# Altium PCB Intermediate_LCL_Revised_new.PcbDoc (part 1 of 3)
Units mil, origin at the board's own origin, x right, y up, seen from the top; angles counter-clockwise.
Board outline 12850 x 6950 mil, 4 copper layers (Top Layer, Lay1, gnd, Bottom Layer), stack 23.756 mil thick; 473 components, 243 nets, 1278 pads, 73 vias.
Unrouted connection lines stored in the file: 289.
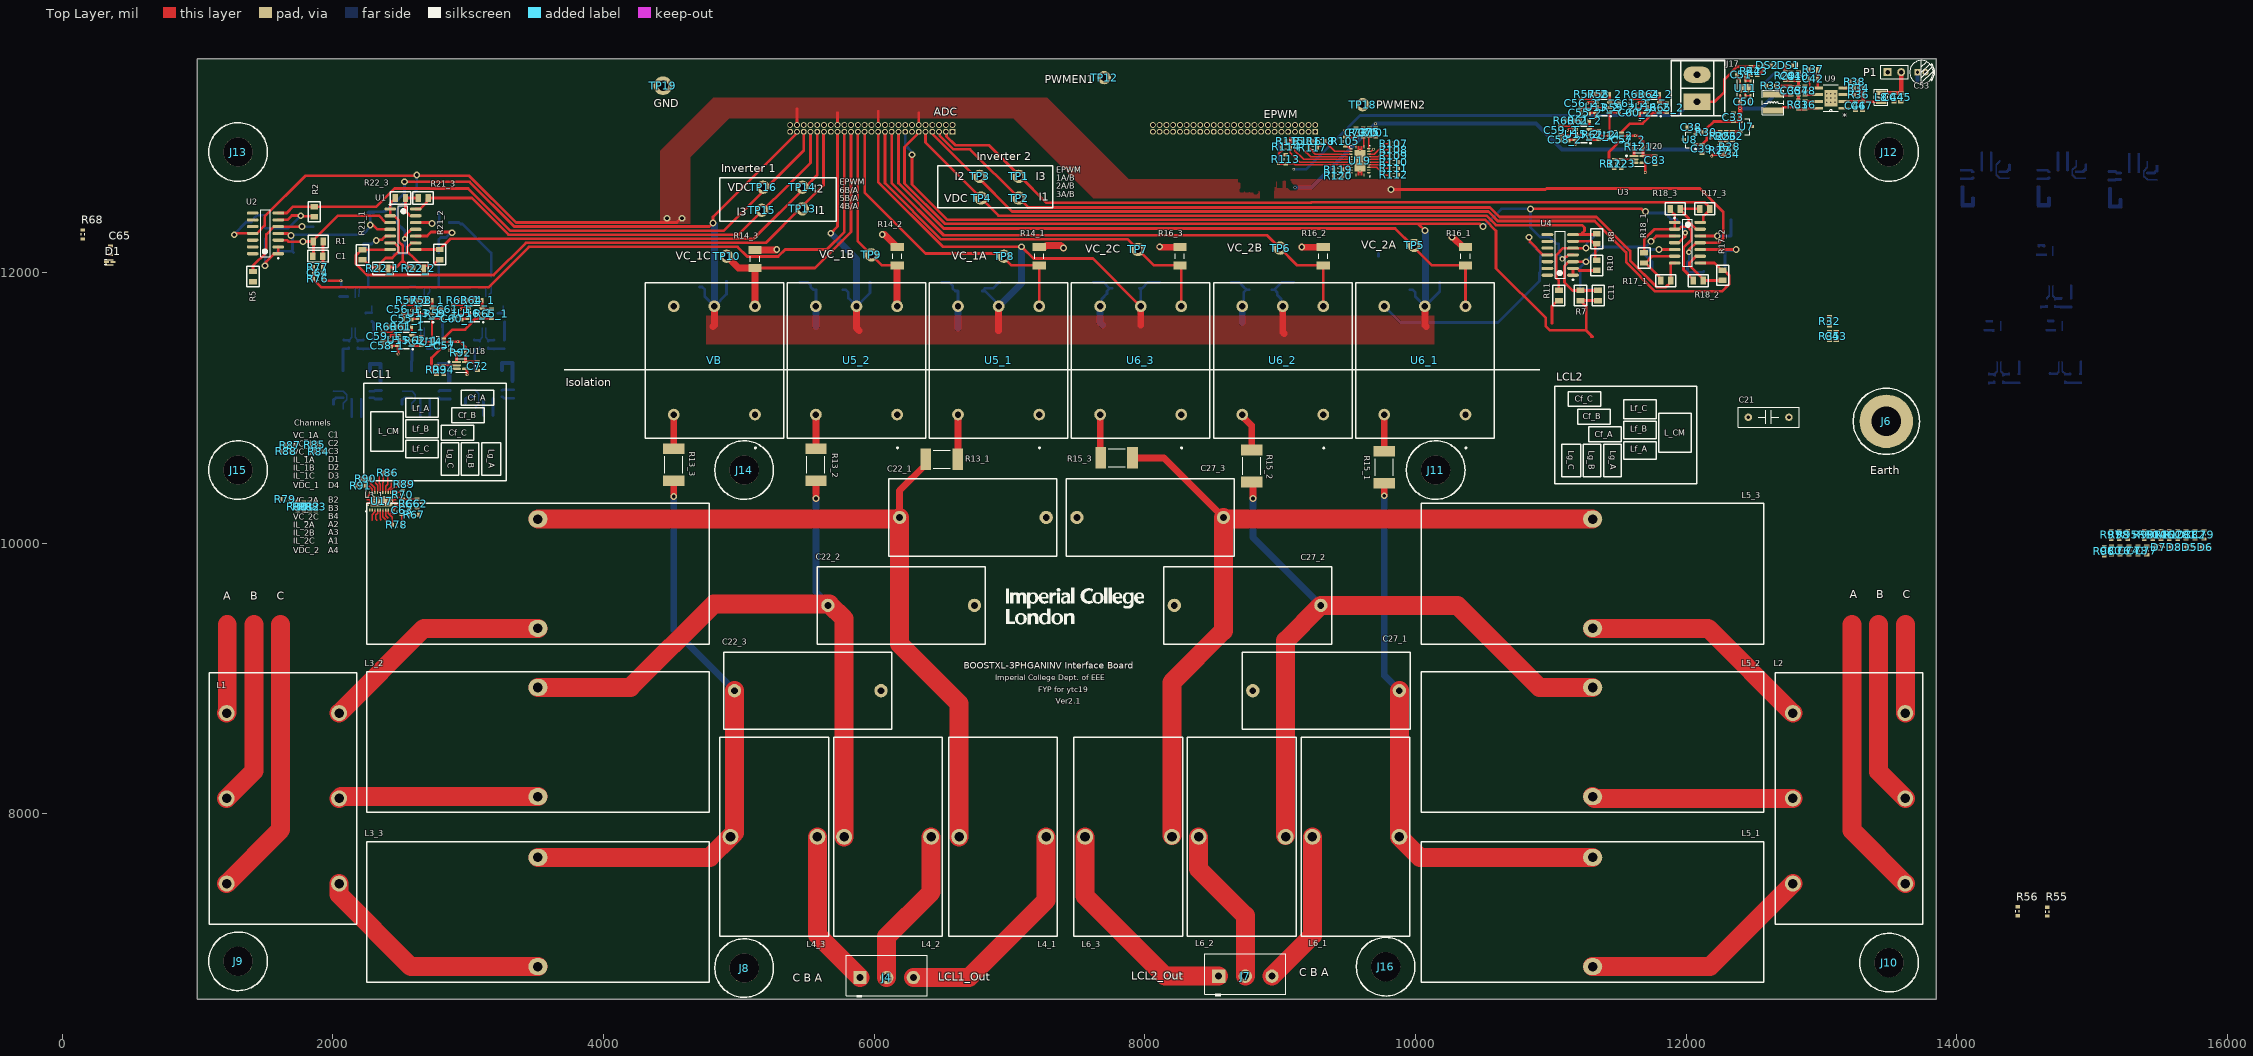
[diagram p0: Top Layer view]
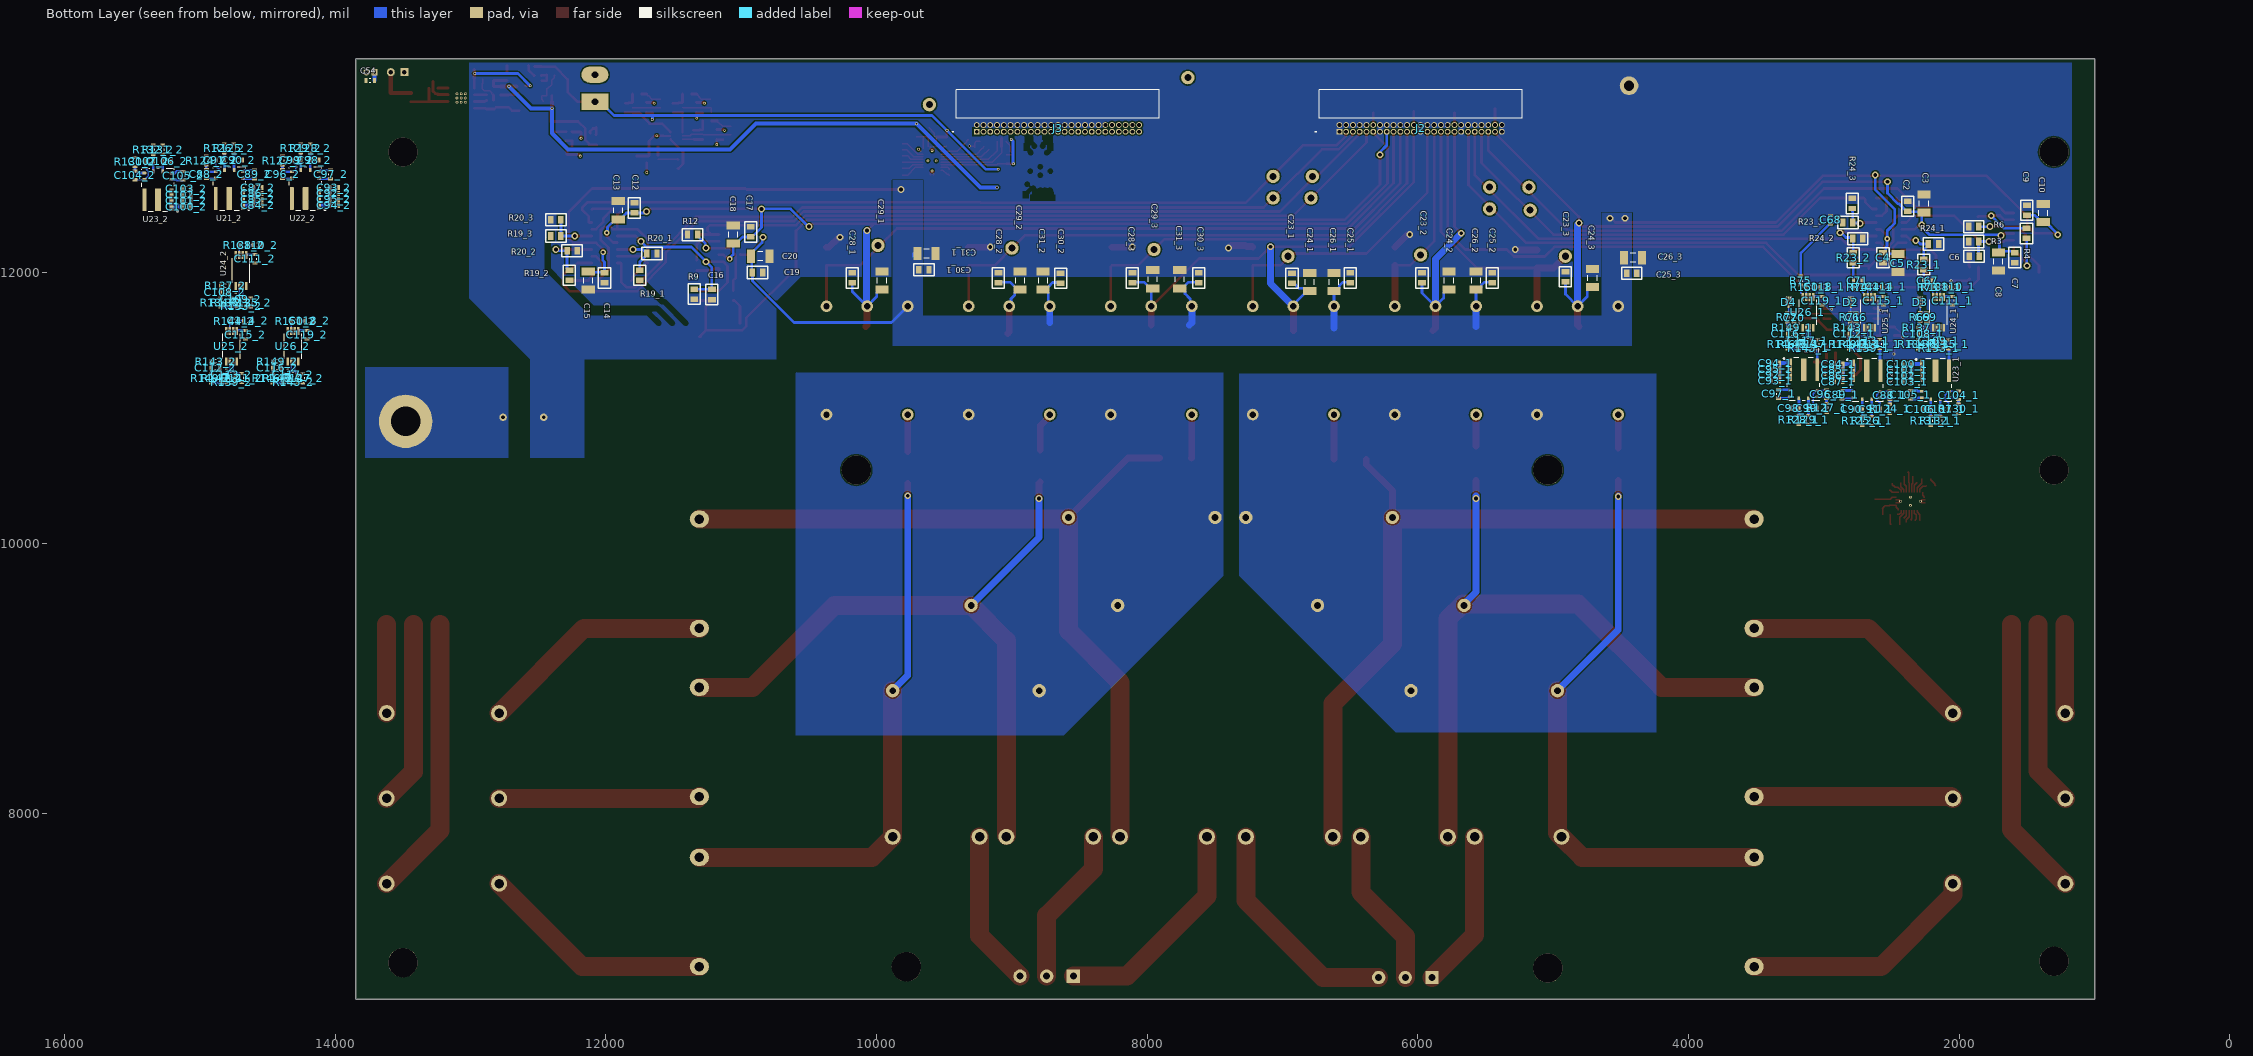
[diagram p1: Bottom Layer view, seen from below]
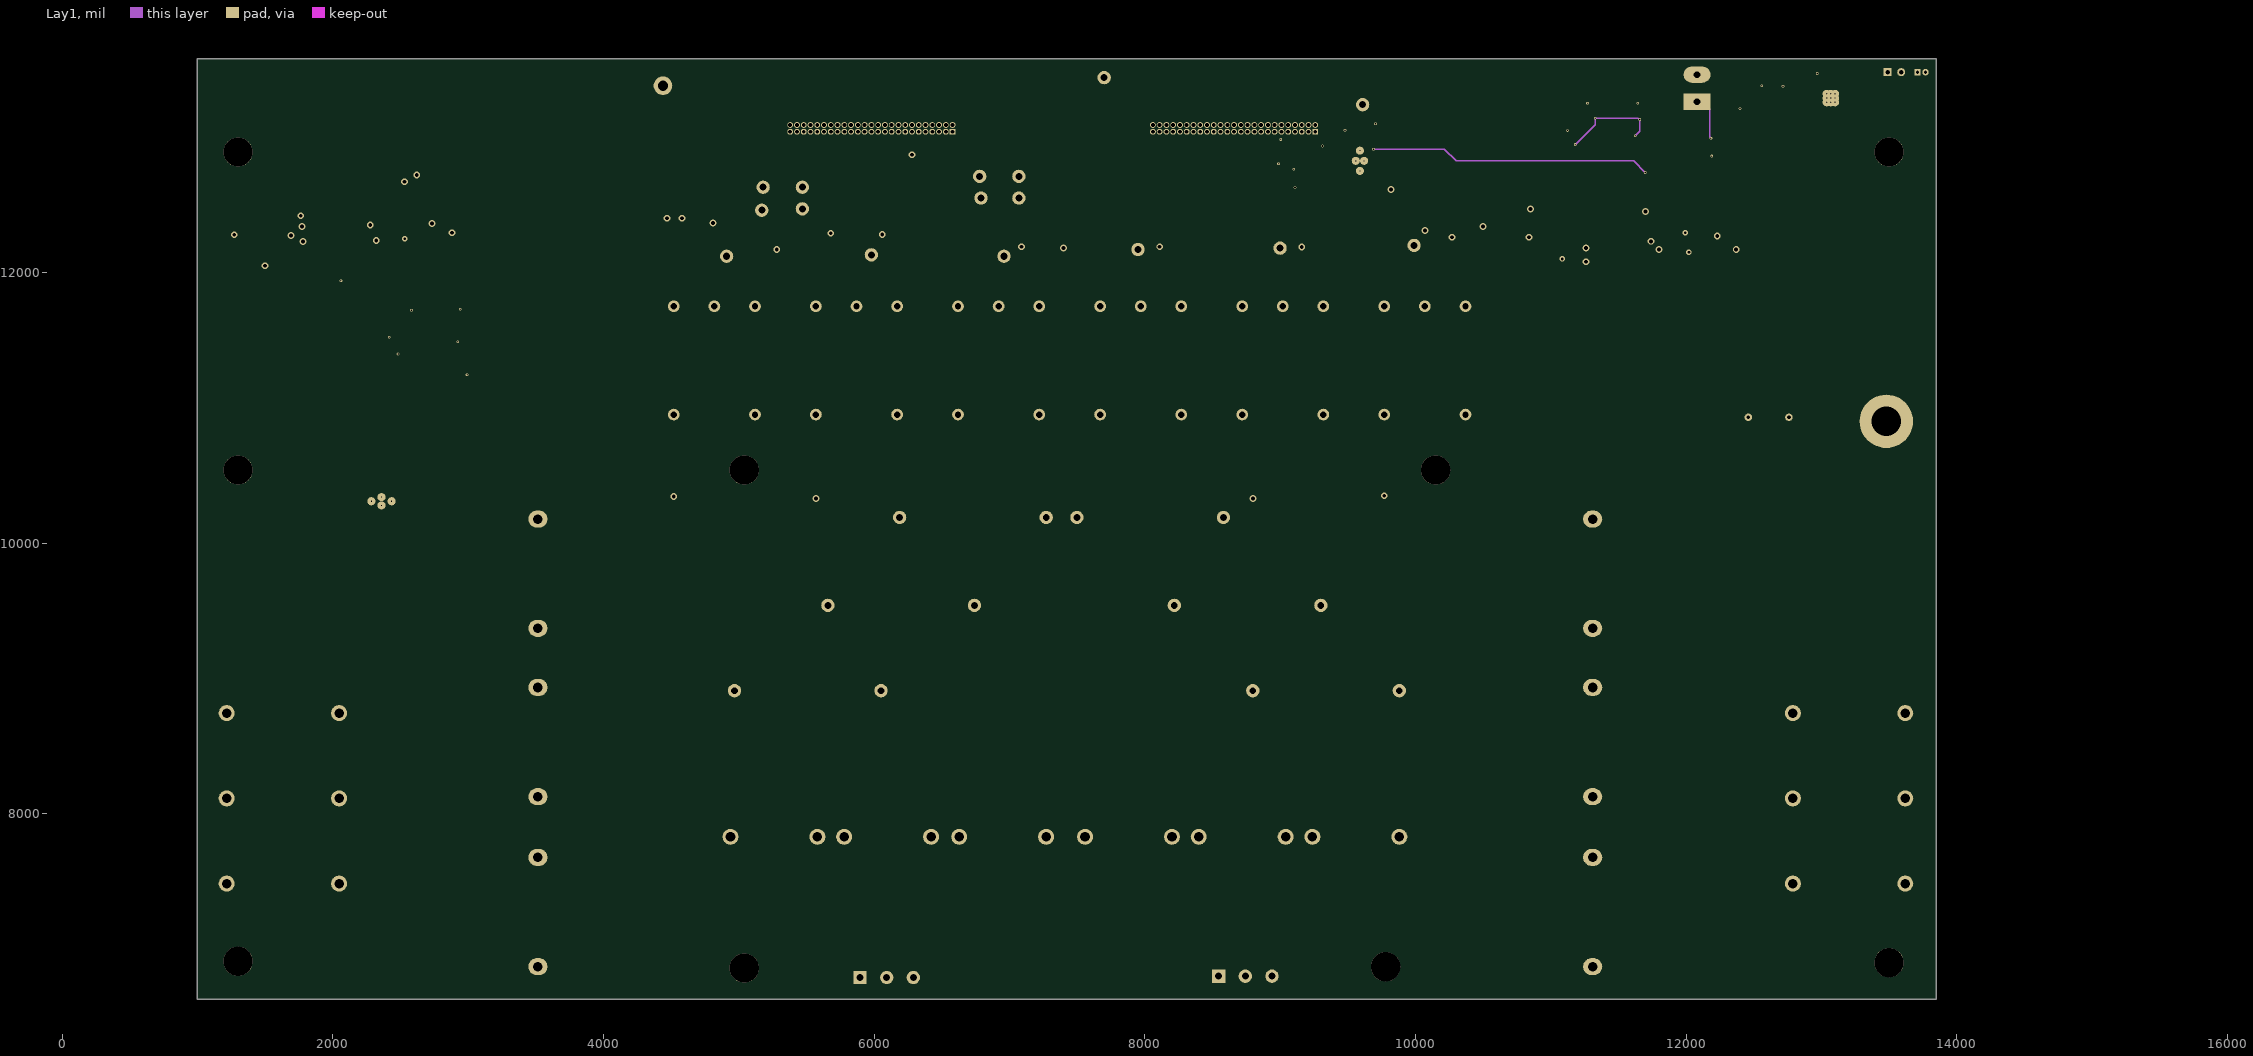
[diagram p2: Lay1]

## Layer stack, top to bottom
Top Solder: solder mask 0.4, Solder Resist, Dk 3.5
Top Layer: signal copper 1.4
Dielectric 2: prepreg 2.8, PP-006, Dk 4.1
Lay1: signal copper 1.378
Dielectric 1: dielectric 12.6, FR-4, Dk 4.8
gnd: signal copper 1.378
Dielectric 3: prepreg 2.8, PP-006, Dk 4.1
Bottom Layer: signal copper 1.4
Bottom Solder: solder mask 0.4, Solder Resist, Dk 3.5

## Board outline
1000,6630 13850,6630 13850,13580 1000,13580

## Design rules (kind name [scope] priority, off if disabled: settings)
Clearance [All] p1: gap=10 ignorepadtopadclearanceinfootprint=FALSE except(0: Arc-Hole Track-Hole SMDPad-Hole THPad-Hole Via-Hole Fill-Hole Poly-Hole Region-Hole Text-Hole; 5: SMDPad-SMDPad SMDPad-THPad THPad-THPad)
Height [All] p1: minheight=0 maxheight=1500 prefheight=500
HoleSize [All] p1: absolutevalues=TRUE maxlimit=250 minlimit=1 maxpercent=80.000 minpercent=20.000
PolygonConnect [All] p1: connectstyle=Direct reliefconductorwidth=10 reliefentries=4 polygonreliefangle="90 Angle" airgapwidth=10
RoomDefinition RoomDefinition_3 [InComponentClass('U_1232') vs False] p1: confinementstyle=ConfineIn formatcopy=TRUE lockcomponents=FALSE outline 14950,11150 14130,11150 14130,12240 14950,12240
RoomDefinition [InComponentClass('U_3Phase Inverter2') vs False] p2: confinementstyle=ConfineIn formatcopy=TRUE lockcomponents=FALSE outline 15515.68,12419.85 13945.68,12419.85 13945.68,12979.85 15515.68,12979.85
RoutingVias [All] p1: holewidth=28 width=50 viastyle="Through Hole" minholewidth=28 minwidth=50 maxholewidth=28 maxwidth=50
SolderMaskExpansion [All] p1: expansion=4 istentingtop=FALSE
Width [All] p1: maxlimit=140 minlimit=10 preferedwidth=10 midlayer1_maxwidth=10 midlayer2_maxwidth=10 minimp=50.000000 maximp=50.000000 favimp=50.000000
28 further rules are at their usual default settings.

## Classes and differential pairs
net class VC_MOTOR_[1..2]: VC_MOTOR_1 VC_MOTOR_2
net class VC_[1..2]: VC_1 VC_2
net class VB_MOTOR_[1..2]: VB_MOTOR_1 VB_MOTOR_2
net class VB_[1..2]: VB_1 VB_2
net class VA_Motor_[1..2]: VA_Motor_1 VA_Motor_2
net class VA_[1..2]: VA_1 VA_2
net class PWM_CL[1..2]: PWM_CL1 PWM_CL2
net class PWM_CH[1..2]: PWM_CH1 PWM_CH2
net class PWM_BL[1..2]: PWM_BL1 PWM_BL2
net class PWM_BH[1..2]: PWM_BH1 PWM_BH2
net class PWM_AL[1..2]: PWM_AL1 PWM_AL2
net class PWM_AH[1..2]: PWM_AH1 PWM_AH2
net class Ph_C[1..2]: Ph_C1 Ph_C2
net class Ph_B[1..2]: Ph_B1 Ph_B2
net class Ph_A[1..2]: Ph_A1 Ph_A2
component class "U_Phase Current Voltage Sense2": C55_2 C56_2 C57_2 C58_2 C59_2 C60_2 C61_2 R57_2 R58_2 R59_2 R60_2 R61_2 R62_2 R63_2 R64_2 R65_2 U13_2 U14_2 U15_2 U16_2
component class "U_Phase Current Voltage Sense1": C55_1 C56_1 C57_1 C58_1 C59_1 C60_1 C61_1 R57_1 R58_1 R59_1 R60_1 R61_1 R62_1 R63_1 R64_1 R65_1 U13_1 U14_1 U15_1 U16_1
net class IComp_[1..2]: IComp_1 IComp_2
net class IC_[1..2]: IC_1 IC_2
net class IB_[1..2]: IB_1 IB_2
net class IA_[1..2]: IA_1 IA_2
component class "U_3Phase Inverter1": C84_1 C85_1 C86_1 C87_1 C88_1 C89_1 C90_1 C91_1 C92_1 C93_1 C94_1 C95_1 C96_1 C97_1 C98_1 C99_1 C100_1 C101_1 C102_1 C103_1 C104_1 C105_1 C106_1 C107_1 R124_1 R125_1 R126_1 R127_1 R128_1 R129_1 R130_1 R131_1 R132_1 U21_1 U22_1 U23_1
component class "U_3Phase Inverter2": C84_2 C85_2 C86_2 C87_2 C88_2 C89_2 C90_2 C91_2 C92_2 C93_2 C94_2 C95_2 C96_2 C97_2 C98_2 C99_2 C100_2 C101_2 C102_2 C103_2 C104_2 C105_2 C106_2 C107_2 R124_2 R125_2 R126_2 R127_2 R128_2 R129_2 R130_2 R131_2 R132_2 U21_2 U22_2 U23_2
component class 3: C62 C63 C64 C65 C66 C67 C68 C69 C70 C71 C72 C73 C74 C75 C76 C77 C78 C79 C80 C81 C82 C83 D1 D2 D3 D4 D5 D6 D7 D8 R66 R67 R68 R69 R70 R71 R72 R73 R74 R75 R76 R77 R78 R79 R80 R81 R82 R83 R84 R85 R87 R88 R92 R93 R94 R95 R96 R97 R98 R99 R100 R101 R102 R103 R104 R105 R106 R107 R108 R109 R110 R111 R112 R113 R114 R115 R116 R117 R118 R119 R120 R121 R122 R123 U18 U19 U20
component class 1: C32 C33 C34 C35 C36 C37 C38 C39 C40 C41 C42 C43 C44 C45 C46 C47 C48 C50 C51 C53 C54 DS1 DS2 J17 L7 L8 P1 R25 R26 R27 R28 R29 R31 R32 R33 R34 R35 R36 R37 R38 R42 R43 R55 R56 U7 U9 U11
channel class "3Phase Inverter2": U_1231 U_1232
channel class "3Phase Inverter1": "U_3Phase Inverter1" "U_3Phase Inverter2"
channel class "Phase Current Voltage Sense": "U_Phase Current Voltage Sense1" "U_Phase Current Voltage Sense2"
component class U_1232: C108_2 C109_2 C110_2 C111_2 C112_2 C113_2 C114_2 C115_2 C116_2 C117_2 C118_2 C119_2 R133_2 R134_2 R135_2 R136_2 R137_2 R138_2 R139_2 R140_2 R141_2 R142_2 R143_2 R144_2 R145_2 R146_2 R147_2 R148_2 R149_2 R150_2 U24_2 U25_2 U26_2
component class U_1231: C108_1 C109_1 C110_1 C111_1 C112_1 C113_1 C114_1 C115_1 C116_1 C117_1 C118_1 C119_1 R133_1 R134_1 R135_1 R136_1 R137_1 R138_1 R139_1 R140_1 R141_1 R142_1 R143_1 R144_1 R145_1 R146_1 R147_1 R148_1 R149_1 R150_1 U24_1 U25_1 U26_1
channel class Fdbk_2: Fdbk_21 Fdbk_22 Fdbk_23
channel class Fdbk_1: Fdbk_11 Fdbk_12 Fdbk_13
net class I_PosB_[1..3]: I_PosB_1 I_PosB_2 I_PosB_3
net class I_PosA_[1..3]: I_PosA_1 I_PosA_2 I_PosA_3
net class I_OutB_[1..3]: I_OutB_1 I_OutB_2 I_OutB_3
net class I_OutA_[1..3]: I_OutA_1 I_OutA_2 I_OutA_3
net class I_NegB_[1..3]: I_NegB_1 I_NegB_2 I_NegB_3
net class I_NegA_[1..3]: I_NegA_1 I_NegA_2 I_NegA_3
net class I_InB_[1..3]: I_InB_1 I_InB_2 I_InB_3
net class I_InA_[1..3]: I_InA_1 I_InA_2 I_InA_3
component class Fdbk_23: R17_3 R18_3 R19_3 R20_3
component class Fdbk_22: R17_2 R18_2 R19_2 R20_2
component class Fdbk_21: R17_1 R18_1 R19_1 R20_1
component class Fdbk_13: R21_3 R22_3 R23_3 R24_3
component class Fdbk_12: R21_2 R22_2 R23_2 R24_2
component class Fdbk_11: R21_1 R22_1 R23_1 R24_1
channel class LCL_2: LCL_21 LCL_22 LCL_23
net class V_termB_[1..3]: V_termB_1 V_termB_2 V_termB_3
net class V_termA_[1..3]: V_termA_1 V_termA_2 V_termA_3
net class V_o_outB_[1..3]: V_o_outB_1 V_o_outB_2 V_o_outB_3
net class V_o_outA_[1..3]: V_o_outA_1 V_o_outA_2 V_o_outA_3
net class V_capB_[1..3]: V_capB_1 V_capB_2 V_capB_3
net class V_capA_[1..3]: V_capA_1 V_capA_2 V_capA_3
component class LCL_23: C27_3 C28_3 C29_3 C30_3 C31_3 L5_3 L6_3 R15_3 R16_3 U6_3
component class LCL_22: C27_2 C28_2 C29_2 C30_2 C31_2 L5_2 L6_2 R15_2 R16_2 U6_2
component class LCL_21: C27_1 C28_1 C29_1 C30_1 C31_1 L5_1 L6_1 R15_1 R16_1 U6_1
channel class LCL_1: LCL_11 LCL_12 LCL_13
component class LCL_13: C22_3 C23_3 C24_3 C25_3 C26_3 L3_3 L4_3 R13_3 R14_3 U5_3
component class LCL_12: C22_2 C23_2 C24_2 C25_2 C26_2 L3_2 L4_2 R13_2 R14_2 U5_2
component class LCL_11: C22_1 C23_1 C24_1 C25_1 C26_1 C31 L3_1 L4_1 R13_1 R14_1 U5_1
component class Intermediate_LCL_Top_20230320: C1 C2 C3 C4 C5 C6 C7 C8 C9 C10 C11 C12 C13 C14 C15 C16 C17 C18 C19 C20 C21 J2 J3 J4 J6 J7 J8 J9 J10 J11 J12 J13 J14 J15 J16 L1 L2 R1 R2 R3 R4 R5 R6 R7 R8 R9 R10 R11 R12 TP1 TP2 TP3 TP4 TP5 TP6 TP7 TP8 TP9 TP10 TP12 TP13 TP14 TP15 TP16 TP18 TP19 U1 U2 U3 U4

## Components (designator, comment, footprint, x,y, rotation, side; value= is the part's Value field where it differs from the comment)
C1 "2.2uF_0805" "0805 Capacitor" 1890,12120 r0 top
C2 "100nF_0805" "0805 Capacitor" 2380,12490 r270 bottom
C3 "4.7uF_1206" "1206 Capacitor" 2260,12510 r270 bottom
C4 "100nF_0805" "0805 Capacitor" 2562.6,12108.86 r90 bottom
C5 "4.7uF_1206" "1206 Capacitor" 2452.6,12068.86 r90 bottom
C6 "2.2uF_0805" "0805 Capacitor" 1890,12120 r180 bottom
C7 "100nF_0805" "0805 Capacitor" 1590,12110 r90 bottom
C8 "4.7uF_1206" "1206 Capacitor" 1710,12080 r90 bottom
C9 "100nF_0805" "0805 Capacitor" 1500,12460 r270 bottom
C10 "4.7uF_1206" "1206 Capacitor" 1380,12440 r270 bottom
C11 "2.2uF_0805" "0805 Capacitor" 11350,11830 r270 top
C12 "100nF_0805" "0805 Capacitor" 11790,12477.4 r270 bottom
C13 "4.7uF_1206" "1206 Capacitor" 11910,12460 r270 bottom
C14 "100nF_0805" "0805 Capacitor" 12010,11960 r90 bottom
C15 "4.7uF_1206" "1206 Capacitor" 12130,11940 r90 bottom
C16 "2.2uF_0805" "0805 Capacitor" 11217.16,11837.4 r90 bottom
C17 "100nF_0805" "0805 Capacitor" 10930,12300 r270 bottom
C18 "4.7uF_1206" "1206 Capacitor" 11060,12280 r270 bottom
C19 "100nF_0805" "0805 Capacitor" 10880,12000 r0 bottom
C20 "4.7uF_1206" "1206 Capacitor" 10860,12120 r0 bottom
C21 "Earth Capacitor" RAD-0.3 12610,10930 r0 top
C22_1 "2.2uF_180V" "Film Capacitor PHE450HF7220JR06L2" 6730,10190 r270 top (schematic designator C22)
C22_2 "2.2uF_180V" "Film Capacitor PHE450HF7220JR06L2" 6200,9540 r270 top (schematic designator C22)
C22_3 "2.2uF_180V" "Film Capacitor PHE450HF7220JR06L2" 5510,8910 r270 top (schematic designator C22)
C23_1 "100nF_0805" "0805 Capacitor" 6930,11958.11 r270 bottom (schematic designator C23)
C23_2 "100nF_0805" "0805 Capacitor" 5970,11960 r270 bottom (schematic designator C23)
C23_3 "100nF_0805" "0805 Capacitor" 4910,11968.11 r270 bottom (schematic designator C23)
C24_1 "4.7uF_1206" "1206 Capacitor" 6800,11930 r270 bottom (schematic designator C24)
C24_2 "4.7uF_1206" "1206 Capacitor" 5770,11940 r270 bottom (schematic designator C24)
C24_3 "4.7uF_1206" "1206 Capacitor" 4710,11960 r270 bottom (schematic designator C24)
C25_1 "100nF_0805" "0805 Capacitor" 6500,11960 r270 bottom (schematic designator C25)
C25_2 "100nF_0805" "0805 Capacitor" 5450,11960 r270 bottom (schematic designator C25)
C25_3 "100nF_0805" "0805 Capacitor" 4420,11993.9 r0 bottom (schematic designator C25)
C26_1 "4.7uF_1206" "1206 Capacitor" 6620,11930 r270 bottom (schematic designator C26)
C26_2 "4.7uF_1206" "1206 Capacitor" 5570,11940 r270 bottom (schematic designator C26)
C26_3 "4.7uF_1206" "1206 Capacitor" 4410,12110 r0 bottom (schematic designator C26)
C27_1 "2.2uF_180V" "Film Capacitor PHE450HF7220JR06L2" 9340,8910 r90 top (schematic designator C27)
C27_2 "2.2uF_180V" "Film Capacitor PHE450HF7220JR06L2" 8760,9540 r90 top (schematic designator C27)
C27_3 "2.2uF_180V" "Film Capacitor PHE450HF7220JR06L2" 8040,10190 r90 top (schematic designator C27)
C28_1 "100nF_0805" "0805 Capacitor" 10180,11960 r270 bottom (schematic designator C28)
C28_2 "100nF_0805" "0805 Capacitor" 9100,11960 r270 bottom (schematic designator C28)
C28_3 "100nF_0805" "0805 Capacitor" 8110,11960 r270 bottom (schematic designator C28)
C29_1 "4.7uF_1206" "1206 Capacitor" 9960,11940 r270 bottom (schematic designator C29)
C29_2 "4.7uF_1206" "1206 Capacitor" 8940,11940 r270 bottom (schematic designator C29)
C29_3 "4.7uF_1206" "1206 Capacitor" 7960,11950 r270 bottom (schematic designator C29)
C30_1 "100nF_0805" "0805 Capacitor" 9650,12020 r0 bottom (schematic designator C30)
C30_2 "100nF_0805" "0805 Capacitor" 8640,11958.11 r270 bottom (schematic designator C30)
C30_3 "100nF_0805" "0805 Capacitor" 7620,11960 r270 bottom (schematic designator C30)
C31_1 "4.7uF_1206" "1206 Capacitor" 9630,12140 r0 bottom (schematic designator C31)
C31_2 "4.7uF_1206" "1206 Capacitor" 8770,11940 r270 bottom (schematic designator C31)
C31_3 "4.7uF_1206" "1206 Capacitor" 7760,11950 r270 bottom (schematic designator C31)
C32 "0.1uF" CAPC1608X06N 12343.82,13007.77 r270 top
C33 "0.1uF" CAPC1608X06N 12350.37,13147.64 r90 top
C34 "2200pF" CAPC1608X06N 12319.58,12871.86 r0 top
C35 "10nF" CAPC1608X06N 12776.68,13343.18 r90 top
C36 "0.01uF" CAPC1608X06N 12880,13240 r270 top
C37 "3300pF" CAPC1608X06N 12830.62,13343.18 r270 top
C38 "0.1uF" CAPC1608X06N 12039.33,13072.19 r180 top value=1uF
C39 "0.1uF" CAPC1608X06N 12117.13,12912.82 r270 top value=1uF
C40 "100uF" CAPC1608X06N 12830.62,13450.52 r270 top
C41 "0.1uF" CAPC1608X06N 12776.68,13450.52 r270 top
C42 "0.01uF" CAPC1608X06N 12940.86,13430.43 r180 top
C43 "0.033uF" CAPC1608X06N 13110,11530 r270 top
C44 "3.3uF" CAPC1608X06N 13536.44,13293.45 r270 top
C45 "100nF" CAPC1608X06N 13586.44,13293.45 r270 top
C46 "100nF" CAPC1608X06N 13252.9,13230.28 r270 top
C47 "3.3uF" CAPC1608X06N 13302.9,13230.28 r90 top
C48 "1uF" CAPC1608X06N 12880.2,13344.03 r270 top
C50 "1uF" CAPC1608X06N 12431.5,13260 r180 top
C51 "100uF" CAPC1608X06N 12406.49,13460 r0 top
C53 "220uF" "CAP 1.5*4*8" 13739.53,13480 r0 top
C54 "3.3uF" CAPC1608X06N 13742.16,13417.1 r180 bottom
C55_1 "0.1uF" CAPC1608X06N 2552.51,11657.49 r180 top (schematic designator C55)
C55_2 "0.1uF" CAPC1608X06N 11254,13179.71 r180 top (schematic designator C55)
C56_1 "2200pF" CAPC1608X06N 2522.51,11727.49 r270 top (schematic designator C56)
C56_2 "2200pF" CAPC1608X06N 11224,13249.71 r270 top (schematic designator C56)
C57_1 "0.1uF" CAPC1608X06N 2872.51,11457.49 r270 top (schematic designator C57)
C57_2 "0.1uF" CAPC1608X06N 11574,12979.71 r270 top (schematic designator C57)
C58_1 "0.1uF" CAPC1608X06N 2402.51,11457.49 r180 top (schematic designator C58)
C58_2 "0.1uF" CAPC1608X06N 11104,12979.71 r180 top (schematic designator C58)
C59_1 "2200pF" CAPC1608X06N 2372.51,11527.49 r270 top (schematic designator C59)
C59_2 "2200pF" CAPC1608X06N 11074,13049.71 r270 top (schematic designator C59)
C60_1 "0.1uF" CAPC1608X06N 2922.51,11657.49 r180 top (schematic designator C60)
C60_2 "0.1uF" CAPC1608X06N 11624,13179.71 r180 top (schematic designator C60)
C61_1 "2200pF" CAPC1608X06N 2892.51,11727.49 r270 top (schematic designator C61)
C61_2 "2200pF" CAPC1608X06N 11594,13249.71 r270 top (schematic designator C61)
C62 "0.1uF" CAPC1608X06N 2621.71,10292.2 r270 top
C63 "0.1uF" CAPC1608X06N 2511.81,10243.11 r270 top
C64 "2200pF" CAPC1608X06N 1890.38,11997.74 r0 top
C65 "2200pF" CAPC1608X06N 355.77,12165.07 r90 top
C66 "2200pF" CAPC1608X06N 2761.35,11667.36 r270 bottom
C67 "2200pF" CAPC1608X06N 2232.08,11939.25 r180 bottom
C68 "2200pF" CAPC1608X06N 2950,12390 r90 bottom
C69 "2200pF" CAPC1608X06N 2242.66,11668.9 r270 bottom
C70 "2200pF" CAPC1608X06N 3220,11666.56 r270 bottom
C71 "2200pF" CAPC1608X06N 2750,11939.25 r180 bottom
C72 "0.1uF" CAPC1608X06N 3070.24,11307.6 r270 top
C73 "0.1uF" CAPC1608X06N 9559.71,13033.87 r90 top
C74 "2200pF" CAPC1608X06N 15273.5,9945.07 r90 top
C75 "0.1uF" CAPC1608X06N 9660.12,13035.64 r90 top
C76 "2200pF" CAPC1608X06N 15208.1,9945.07 r90 top
C77 "2200pF" CAPC1608X06N 15404.31,9945.07 r90 top
C78 "2200pF" CAPC1608X06N 15338.91,9945.07 r90 top
C79 "2200pF" CAPC1608X06N 15826.69,10062.69 r90 top
C80 "2200pF" CAPC1608X06N 15142.7,9945.07 r90 top
C81 "2200pF" CAPC1608X06N 15695.88,10062.69 r90 top
C82 "2200pF" CAPC1608X06N 15761.28,10062.69 r90 top
C83 "0.1uF" CAPC1608X06N 11771.73,12829.81 r270 top
C84_1 "3.3uF" CAPC1608X06N 2892.06,11323.24 r180 bottom (schematic designator C84)
C84_2 "3.3uF" CAPC1608X06N 14573.09,12497 r0 bottom (schematic designator C84)
C85_1 "100nF" CAPC1608X06N 2892.06,11279.91 r0 bottom (schematic designator C85)
C85_2 "100nF" CAPC1608X06N 14573.09,12540.33 r180 bottom (schematic designator C85)
C86_1 "3.3uF" CAPC1608X06N 2892.06,11236.57 r180 bottom (schematic designator C86)
C86_2 "3.3uF" CAPC1608X06N 14573.09,12583.67 r0 bottom (schematic designator C86)
C87_1 "3.3uF" CAPC1608X06N 2892.06,11193.24 r180 bottom (schematic designator C87)
C87_2 "3.3uF" CAPC1608X06N 14573.09,12627 r0 bottom (schematic designator C87)
C88_1 "2.2uF" CAPC1608X06N 2512.06,11093.24 r270 bottom (schematic designator C88)
C88_2 "2.2uF" CAPC1608X06N 14953.09,12727 r90 bottom (schematic designator C88)
C89_1 "100nF" CAPC1608X06N 2867.02,11096 r270 bottom (schematic designator C89)
C89_2 "100nF" CAPC1608X06N 14598.13,12724.24 r90 bottom (schematic designator C89)
C90_1 "47pF" CAPC1608X06N 2748.5,10990 r0 bottom (schematic designator C90)
C90_2 "47pF" CAPC1608X06N 14716.65,12830.24 r180 bottom (schematic designator C90)
C91_1 "47pF" CAPC1608X06N 2615.09,10990 r180 bottom (schematic designator C91)
C91_2 "47pF" CAPC1608X06N 14850.06,12830.24 r0 bottom (schematic designator C91)
C92_1 "3.3uF" CAPC1608X06N 3360,11243.25 r180 bottom (schematic designator C92)
C92_2 "3.3uF" CAPC1608X06N 14010,12583.67 r0 bottom (schematic designator C92)
C93_1 "100nF" CAPC1608X06N 3360,11199.92 r0 bottom (schematic designator C93)
C93_2 "100nF" CAPC1608X06N 14010,12627 r180 bottom (schematic designator C93)
C94_1 "3.3uF" CAPC1608X06N 3360,11329.92 r180 bottom (schematic designator C94)
C94_2 "3.3uF" CAPC1608X06N 14010,12497 r0 bottom (schematic designator C94)
C95_1 "3.3uF" CAPC1608X06N 3360,11286.59 r180 bottom (schematic designator C95)
C95_2 "3.3uF" CAPC1608X06N 14010,12540.33 r0 bottom (schematic designator C95)
C96_1 "2.2uF" CAPC1608X06N 2980,11099.92 r270 bottom (schematic designator C96)
C96_2 "2.2uF" CAPC1608X06N 14390,12727 r90 bottom (schematic designator C96)
C97_1 "100nF" CAPC1608X06N 3334.96,11102.69 r270 bottom (schematic designator C97)
C97_2 "100nF" CAPC1608X06N 14035.04,12724.24 r90 bottom (schematic designator C97)
C98_1 "47pF" CAPC1608X06N 3216.44,10996.68 r0 bottom (schematic designator C98)
C98_2 "47pF" CAPC1608X06N 14153.56,12830.24 r180 bottom (schematic designator C98)
C99_1 "47pF" CAPC1608X06N 3083.03,10996.68 r180 bottom (schematic designator C99)
C99_2 "47pF" CAPC1608X06N 14286.97,12830.24 r0 bottom (schematic designator C99)
C100_1 "3.3uF" CAPC1608X06N 2385.15,11323.24 r180 bottom (schematic designator C100)
C100_2 "3.3uF" CAPC1608X06N 15100,12487 r0 bottom (schematic designator C100)
C101_1 "100nF" CAPC1608X06N 2385.15,11279.91 r0 bottom (schematic designator C101)
C101_2 "100nF" CAPC1608X06N 15100,12530.33 r180 bottom (schematic designator C101)
C102_1 "3.3uF" CAPC1608X06N 2385.15,11236.57 r180 bottom (schematic designator C102)
C102_2 "3.3uF" CAPC1608X06N 15100,12573.67 r0 bottom (schematic designator C102)
C103_1 "3.3uF" CAPC1608X06N 2385.15,11193.24 r180 bottom (schematic designator C103)
C103_2 "3.3uF" CAPC1608X06N 15100,12617 r0 bottom (schematic designator C103)
C104_1 "2.2uF" CAPC1608X06N 2005.15,11093.24 r270 bottom (schematic designator C104)
C104_2 "2.2uF" CAPC1608X06N 15480,12717 r90 bottom (schematic designator C104)
C105_1 "100nF" CAPC1608X06N 2360.12,11096 r270 bottom (schematic designator C105)
C105_2 "100nF" CAPC1608X06N 15125.04,12714.24 r90 bottom (schematic designator C105)
C106_1 "47pF" CAPC1608X06N 2241.6,10990 r0 bottom (schematic designator C106)
C106_2 "47pF" CAPC1608X06N 15243.56,12820.24 r180 bottom (schematic designator C106)
C107_1 "47pF" CAPC1608X06N 2108.19,10990 r180 bottom (schematic designator C107)
C107_2 "47pF" CAPC1608X06N 15376.97,12820.24 r0 bottom (schematic designator C107)
C108_1 "0.033uF" CAPC1608X06N 2271.1,11546.08 r180 bottom (schematic designator C108)
C108_2 "0.033uF" CAPC1608X06N 14815.33,11855.16 r180 bottom (schematic designator C108)
C109_1 "1500pF" CAPC1608X06N 2153,11494.04 r180 bottom (schematic designator C109)
C109_2 "1500pF" CAPC1608X06N 14697.23,11803.11 r180 bottom (schematic designator C109)
C110_1 "0.1uF" CAPC1608X06N 2031.14,11893.46 r180 bottom (schematic designator C110)
C110_2 "0.1uF" CAPC1608X06N 14575.37,12202.54 r180 bottom (schematic designator C110)
C111_1 "0.1uF" CAPC1608X06N 2050,11791.5 r90 bottom (schematic designator C111)
C111_2 "0.1uF" CAPC1608X06N 14594.23,12100.57 r90 bottom (schematic designator C111)
C112_1 "0.033uF" CAPC1608X06N 2781.1,11546.08 r180 bottom (schematic designator C112)
C112_2 "0.033uF" CAPC1608X06N 14885.33,11295.16 r180 bottom (schematic designator C112)
C113_1 "1500pF" CAPC1608X06N 2665.77,11494.04 r180 bottom (schematic designator C113)
C113_2 "1500pF" CAPC1608X06N 14770,11243.11 r180 bottom (schematic designator C113)
C114_1 "0.1uF" CAPC1608X06N 2541.14,11893.46 r180 bottom (schematic designator C114)
C114_2 "0.1uF" CAPC1608X06N 14645.37,11642.54 r180 bottom (schematic designator C114)
C115_1 "0.1uF" CAPC1608X06N 2560,11791.5 r90 bottom (schematic designator C115)
C115_2 "0.1uF" CAPC1608X06N 14664.23,11540.57 r90 bottom (schematic designator C115)
C116_1 "0.033uF" CAPC1608X06N 3236.42,11546.08 r180 bottom (schematic designator C116)
C116_2 "0.033uF" CAPC1608X06N 14430.65,11295.16 r180 bottom (schematic designator C116)
C117_1 "1500pF" CAPC1608X06N 3118.32,11494.04 r180 bottom (schematic designator C117)
C117_2 "1500pF" CAPC1608X06N 14312.55,11243.11 r180 bottom (schematic designator C117)
C118_1 "0.1uF" CAPC1608X06N 2996.46,11893.46 r180 bottom (schematic designator C118)
C118_2 "0.1uF" CAPC1608X06N 14190.69,11642.54 r180 bottom (schematic designator C118)
C119_1 "0.1uF" CAPC1608X06N 3015.32,11791.5 r90 bottom (schematic designator C119)
C119_2 "0.1uF" CAPC1608X06N 14209.55,11540.57 r90 bottom (schematic designator C119)
D1 "1PS79SB70,115" SOD-523_L1.2-W0.8-LS1.6-RD 351.94,12076.02 r0 top
D2 "1PS79SB70,115" SOD-523_L1.2-W0.8-LS1.6-RD 2800,11780 r270 bottom
D3 "1PS79SB70,115" SOD-523_L1.2-W0.8-LS1.6-RD 2287.01,11780 r270 bottom
D4 "1PS79SB70,115" SOD-523_L1.2-W0.8-LS1.6-RD 3260,11780 r270 bottom
D5 "1PS79SB70,115" SOD-523_L1.2-W0.8-LS1.6-RD 15723.54,9970.63 r0 top
D6 "1PS79SB70,115" SOD-523_L1.2-W0.8-LS1.6-RD 15838.16,9970.63 r0 top
D7 "1PS79SB70,115" SOD-523_L1.2-W0.8-LS1.6-RD 15494.32,9970.63 r0 top
D8 "1PS79SB70,115" SOD-523_L1.2-W0.8-LS1.6-RD 15608.93,9970.63 r0 top
DS1 "TLMP1100-GS08" VISH-TLMX1100_V 12760,13530 r0 top
DS2 "TLMP1100-GS08" VISH-TLMX1100_V 12601.5,13530 r0 top
J2 "ADC" SHF-125-01-L-D-RA 5980,13060 r180 bottom
J3 "EPWM" SHF-125-01-L-D-RA 8660,13060 r180 bottom
J4 "LCL1_Out" "3 Pin Terminal" 6093.15,6790 r0 top
J6 "M5 Earthing Hole" "M5 Earthing Hole" 13480,10900 r0 top
J7 "LCL2_Out" "3 Pin Terminal" 8743.15,6800 r0 top
J8 "M5 Mounting Hole" "M5 Mounting Hole" 5040,6860 r0 top
J9 "M5 Mounting Hole" "M5 Mounting Hole" 1300,6910 r0 top
J10 "M5 Mounting Hole" "M5 Mounting Hole" 13500,6900 r0 top
J11 "M5 Mounting Hole" "M5 Mounting Hole" 10150,10540 r0 top
J12 "M5 Mounting Hole" "M5 Mounting Hole" 13500,12890 r0 top
J13 "M5 Mounting Hole" "M5 Mounting Hole" 1300,12890 r0 top
J14 "M5 Mounting Hole" "M5 Mounting Hole" 5040,10540 r0 top
J15 "M5 Mounting Hole" "M5 Mounting Hole" 1300,10540 r0 top
J16 "M5 Mounting Hole" "M5 Mounting Hole" 9780,6870 r0 top
J17 "CON2" DG1282-5.0 12081.18,13361.79 r90 top
L1 "30mH CM" "CM Choke Custom" 1631.06,8114 r0 top
L2 "30mH CM" "CM Choke Custom" 13204.65,8114 r180 top
L3_1 "4mH" "4mH Custom" 3515.71,9774 r90 top (schematic designator L3)
L3_2 "4mH" "4mH Custom" 3515.71,8530 r90 top (schematic designator L3)
L3_3 "4mH" "4mH Custom" 3515.71,7274 r90 top (schematic designator L3)
L4_1 "380uH" "380uH Custom" 6950,7830 r0 top (schematic designator L4)
L4_2 "380uH" "380uH Custom" 6100,7830 r0 top (schematic designator L4)
L4_3 "380uH" "380uH Custom" 5260,7830 r0 top (schematic designator L4)
L5_1 "4mH" "4mH Custom" 11310,7274 r90 top (schematic designator L5)
L5_2 "4mH" "4mH Custom" 11310,8530 r90 top (schematic designator L5)
L5_3 "4mH" "4mH Custom" 11310,9774 r90 top (schematic designator L5)
L6_1 "380uH" "380uH Custom" 9560,7830 r180 top (schematic designator L6)
L6_2 "380uH" "380uH Custom" 8720,7830 r180 top (schematic designator L6)
L6_3 "380uH" "380uH Custom" 7880,7830 r180 top (schematic designator L6)
L7 "100uH" NR4018 12642.82,13255.09 r90 top
L8 "33uH" NR2520 13441.76,13295.15 r270 top
P1 "Header 2" HDR1X2 13490,13480 r0 top
R1 "20k_0805" "0805 Resistor" 1892.6,12228.86 r0 top
R2 "200k_0805" "0805 Resistor" 1862.6,12448.86 r270 top
R3 "20k_0805" "0805 Resistor" 1892.6,12228.86 r180 bottom
R4 "10k_0805" "0805 Resistor" 1502.6,12288.86 r90 bottom
R5 "10k_0805" "0805 Resistor" 1410,11970 r90 top
R6 "200k_0805" "0805 Resistor" 1892.6,12338.86 r0 bottom
R7 "20k_0805" "0805 Resistor" 11220,11830 r270 top
R8 "200k_0805" "0805 Resistor" 11340,12250 r270 top
R9 "20k_0805" "0805 Resistor" 11347.16,11840 r90 bottom
R10 "10k_0805" "0805 Resistor" 11340,12052.6 r90 top
R11 "10k_0805" "0805 Resistor" 11060,11830 r90 top
R12 "200k_0805" "0805 Resistor" 11360,12280 r0 bottom
R13_1 "10k_2512" "2512 Resistor" 6500,10620 r0 top (schematic designator R13)
R13_2 "10k_2512" "2512 Resistor" 5570,10580 r90 top (schematic designator R13)
R13_3 "10k_2512" "2512 Resistor" 4520,10580 r90 top (schematic designator R13)
R14_1 "130_1206" "1206 Resistor" 7220,12120 r270 top (schematic designator R14)
R14_2 "130_1206" "1206 Resistor" 6170,12120 r270 top (schematic designator R14)
R14_3 "130_1206" "1206 Resistor" 5120,12100 r270 top (schematic designator R14)
R15_1 "10k_2512" "2512 Resistor" 9770,10560 r90 top (schematic designator R15)
R15_2 "10k_2512" "2512 Resistor" 8790,10570 r90 top (schematic designator R15)
R15_3 "10k_2512" "2512 Resistor" 7791.89,10630 r180 top (schematic designator R15)
R16_1 "130_1206" "1206 Resistor" 10370,12120 r270 top (schematic designator R16)
R16_2 "130_1206" "1206 Resistor" 9320,12120 r270 top (schematic designator R16)
R16_3 "130_1206" "1206 Resistor" 8260,12120 r270 top (schematic designator R16)
R17_1 "200k_0805" "0805 Resistor" 11850,11940 r0 top (schematic designator R17)
R17_2 "200k_0805" "0805 Resistor" 12270,11980 r90 top (schematic designator R17)
R17_3 "200k_0805" "0805 Resistor" 12137.4,12470 r0 top (schematic designator R17)
R18_1 "10k_0805" "0805 Resistor" 11690,12107.4 r270 top (schematic designator R18)
R18_2 "10k_0805" "0805 Resistor" 12090,11940 r0 top (schematic designator R18)
R18_3 "10k_0805" "0805 Resistor" 11920,12470 r0 top (schematic designator R18)
R19_1 "10k_0805" "0805 Resistor" 11750,11980 r90 bottom (schematic designator R19)
R19_2 "10k_0805" "0805 Resistor" 12270,11980 r90 bottom (schematic designator R19)
R19_3 "10k_0805" "0805 Resistor" 12370,12270 r180 bottom (schematic designator R19)
R20_1 "200k_0805" "0805 Resistor" 11660,12140 r0 bottom (schematic designator R20)
R20_2 "200k_0805" "0805 Resistor" 12250,12160 r0 bottom (schematic designator R20)
R20_3 "200k_0805" "0805 Resistor" 12370,12390 r180 bottom (schematic designator R20)
R21_1 "200k_0805" "0805 Resistor" 2220,12130 r90 top (schematic designator R21)
R21_2 "200k_0805" "0805 Resistor" 2790,12132.6 r90 top (schematic designator R21)
R21_3 "200k_0805" "0805 Resistor" 2667.4,12550 r0 top (schematic designator R21)
R22_1 "10k_0805" "0805 Resistor" 2370,12030 r180 top (schematic designator R22)
R22_2 "10k_0805" "0805 Resistor" 2630,12030 r0 top (schematic designator R22)
R22_3 "10k_0805" "0805 Resistor" 2500,12550 r0 top (schematic designator R22)
R23_1 "10k_0805" "0805 Resistor" 2262.6,12058.86 r90 bottom (schematic designator R23)
R23_2 "10k_0805" "0805 Resistor" 2782.6,12108.86 r90 bottom (schematic designator R23)
R23_3 "10k_0805" "0805 Resistor" 2822.6,12368.86 r180 bottom (schematic designator R23)
R24_1 "200k_0805" "0805 Resistor" 2190,12210 r0 bottom (schematic designator R24)
R24_2 "200k_0805" "0805 Resistor" 2750,12250 r0 bottom (schematic designator R24)
R24_3 "200k_0805" "0805 Resistor" 2790,12510 r270 bottom (schematic designator R24)
R25 "0" RESC1608X05N 12251.95,13006.39 r90 top value=1MΩ(1%)
R26 "0" RESC1608X05N 12295.55,13007.01 r270 top value=1MΩ(1%)
R27 "54.9k" RESC1608X05N 12250.7,12904.25 r90 top value=1MΩ(1%)
R28 "274k" RESC1608X05N 12321.09,12927.29 r180 top value=1MΩ(1%)
R29 "16.5k" RESC1608X05N 12731.2,13452.15 r270 top value=1MΩ(1%)
R30 "0" RESC1608X05N 12150.72,13037.79 r0 top value=1MΩ(1%)
R31 "68k" RESC1608X05N 12830.15,13240.75 r270 top value=1MΩ(1%)
R32 "100k" RESC1608X05N 13060,11640 r90 top value=1MΩ(1%)
R33 "10.0k" RESC1608X05N 12628.6,13379.54 r0 top value=1MΩ(1%)
R34 "113k" RESC1608X05N 13276.11,13361.79 r180 top value=1MΩ(1%)
R35 "4.22k" RESC1608X05N 13060,11530 r90 top value=1MΩ(1%)
R36 "51.0k" RESC1608X05N 13276.41,13315.08 r180 top value=1MΩ(1%)
R37 "3.24k" RESC1608X05N 12940,13500 r0 top value=1MΩ(1%)
R38 "16.5k" RESC1608X05N 13245.08,13411.14 r0 top value=1MΩ(1%)
R42 "0" RESC1608X05N 12477.05,13488.2 r90 top value=1MΩ(1%)
R43 "10.0k" RESC1608X05N 12527.45,13488.58 r90 top value=1MΩ(1%)
R55 "0" RESC1608X05N 14670,7277 r90 top value=1MΩ(1%)
R56 "0" RESC1608X05N 14450,7280 r90 top value=1MΩ(1%)
R57_1 "20" RESC1608X05N 2592.51,11796.24 r180 top value=1MΩ(1%) (schematic designator R57)
R57_2 "20" RESC1608X05N 11294,13318.46 r180 top value=1MΩ(1%) (schematic designator R57)
R58_1 "10.0k" RESC1608X05N 2699.4,11796.24 r180 top value=1MΩ(1%) (schematic designator R58)
R58_2 "10.0k" RESC1608X05N 11400.89,13318.46 r180 top value=1MΩ(1%) (schematic designator R58)
R59_1 "332k" RESC1608X05N 2802.67,11695 r90 top value=1MΩ(1%) (schematic designator R59)
R59_2 "332k" RESC1608X05N 11504.16,13217.22 r90 top value=1MΩ(1%) (schematic designator R59)
R60_1 "20" RESC1608X05N 2442.51,11597.49 r180 top value=1MΩ(1%) (schematic designator R60)
R60_2 "20" RESC1608X05N 11144,13119.71 r180 top value=1MΩ(1%) (schematic designator R60)
R61_1 "10.0k" RESC1608X05N 2549.4,11597.49 r180 top value=1MΩ(1%) (schematic designator R61)
R61_2 "10.0k" RESC1608X05N 11250.89,13119.71 r180 top value=1MΩ(1%) (schematic designator R61)
R62_1 "332k" RESC1608X05N 2652.67,11495.01 r90 top value=1MΩ(1%) (schematic designator R62)
R62_2 "332k" RESC1608X05N 11354.16,13017.22 r90 top value=1MΩ(1%) (schematic designator R62)
R63_1 "20" RESC1608X05N 2962.51,11796.24 r180 top value=1MΩ(1%) (schematic designator R63)
R63_2 "20" RESC1608X05N 11664,13318.46 r180 top value=1MΩ(1%) (schematic designator R63)
R64_1 "10.0k" RESC1608X05N 3069.4,11796.24 r180 top value=1MΩ(1%) (schematic designator R64)
R64_2 "10.0k" RESC1608X05N 11770.89,13318.46 r180 top value=1MΩ(1%) (schematic designator R64)
R65_1 "332k" RESC1608X05N 3172.67,11695 r90 top value=1MΩ(1%) (schematic designator R65)
R65_2 "332k" RESC1608X05N 11856.67,13217.32 r90 top value=1MΩ(1%) (schematic designator R65)
R66 "0" RESC1608X05N 2568.86,10290.59 r90 top value=K
R67 "0" RESC1608X05N 2601.04,10208.77 r0 top value=K
R68 "20" RESC1608X05N 153.66,12281.19 r90 top value=1MΩ(1%)
R69 "20" RESC1608X05N 2287.01,11670.4 r90 bottom value=1MΩ(1%)
R70 "10.0k" RESC1608X05N 2515.96,10356.86 r90 top value=1MΩ(1%)
R71 "20" RESC1608X05N 2803.49,11668.06 r90 bottom value=1MΩ(1%)
R72 "20" RESC1608X05N 3270,11668.06 r90 bottom value=1MΩ(1%)
R73 "20" RESC1608X05N 2230,11890 r0 bottom value=1MΩ(1%)
R74 "20" RESC1608X05N 2750,11890 r0 bottom value=1MΩ(1%)
R75 "20" RESC1608X05N 3170,11940 r90 bottom value=1MΩ(1%)
R76 "20" RESC1608X05N 1889.86,11954.49 r180 top value=1MΩ(1%)
R77 "20" RESC1608X05N 1890,12040 r0 top value=1MΩ(1%)
R78 "10.0k" RESC1608X05N 2473.61,10134.8 r0 top value=1MΩ(1%)
R79 "10.0k" RESC1608X05N 1649.94,10324.8 r180 top value=1MΩ(1%)
R80 "10.0k" RESC1608X05N 1742.8,10270 r270 top value=1MΩ(1%)
R81 "10.0k" RESC1608X05N 1786.13,10270 r270 top value=1MΩ(1%)
R82 "10.0k" RESC1608X05N 1829.46,10270 r270 top value=1MΩ(1%)
R83 "10.0k" RESC1608X05N 1872.8,10270 r270 top value=1MΩ(1%)
R84 "10.0k" RESC1608X05N 1895.97,10676.47 r180 top value=1MΩ(1%)
R85 "10.0k" RESC1608X05N 1866.3,10726.6 r180 top value=1MΩ(1%)
R86 "10.0k" RESC1608X05N 2406.92,10519.77 r180 top value=1MΩ(1%)
R87 "10.0k" RESC1608X05N 1684.18,10725.09 r180 top value=1MΩ(1%)
R88 "10.0k" RESC1608X05N 1655.95,10677.69 r0 top value=1MΩ(1%)
R89 "10.0k" RESC1608X05N 2527.61,10435.87 r180 top value=1MΩ(1%)
R90 "10.0k" RESC1608X05N 2244.26,10475.08 r180 top value=1MΩ(1%)
R91 "10.0k" RESC1608X05N 2206.97,10425.73 r180 top value=1MΩ(1%)
R92 "10.0k" RESC1608X05N 2947,11406.78 r180 top value=1MΩ(1%)
R93 "0" RESC1608X05N 2766.43,11279.91 r90 top value=1MΩ(1%)
R94 "10.0k" RESC1608X05N 2820.48,11279.91 r90 top value=1MΩ(1%)
R95 "20" RESC1608X05N 15263.66,10061.19 r90 top value=1MΩ(1%)
R96 "20" RESC1608X05N 15090,9940 r270 top value=1MΩ(1%)
R97 "20" RESC1608X05N 15140.73,10061.19 r90 top value=1MΩ(1%)
R98 "20" RESC1608X05N 15202.2,10061.19 r90 top value=1MΩ(1%)
R99 "20" RESC1608X05N 15386.59,10061.19 r90 top value=1MΩ(1%)
R100 "0" RESC1608X05N 9615.24,13034.28 r90 top value=K
R101 "0" RESC1608X05N 9706.15,13034.28 r90 top value=K
R102 "20" RESC1608X05N 15570.98,10061.19 r90 top value=1MΩ(1%)
R103 "20" RESC1608X05N 15632.45,10061.19 r90 top value=1MΩ(1%)
R104 "20" RESC1608X05N 15448.06,10061.19 r90 top value=1MΩ(1%)
R105 "10.0k" RESC1608X05N 9481.25,12968.24 r270 top value=1MΩ(1%)
R106 "20" RESC1608X05N 15509.52,10061.19 r90 top value=1MΩ(1%)
R107 "10.0k" RESC1608X05N 9841.68,12953.11 r0 top value=1MΩ(1%)
R108 "10.0k" RESC1608X05N 9841.68,12907.11 r0 top value=1MΩ(1%)
R109 "10.0k" RESC1608X05N 9841.68,12861.11 r0 top value=1MΩ(1%)
R110 "10.0k" RESC1608X05N 9841.68,12815.11 r0 top value=1MΩ(1%)
R111 "10.0k" RESC1608X05N 9841.68,12769.11 r0 top value=1MΩ(1%)
R112 "10.0k" RESC1608X05N 9841.68,12723.11 r0 top value=1MΩ(1%)
R113 "10.0k" RESC1608X05N 9042.71,12837.18 r270 top value=1MΩ(1%)
R114 "10.0k" RESC1608X05N 9043.93,12927.35 r0 top value=1MΩ(1%)
R115 "10.0k" RESC1608X05N 9076.15,12969.4 r0 top value=1MΩ(1%)
R116 "10.0k" RESC1608X05N 9202.78,12970.05 r0 top value=1MΩ(1%)
R117 "10.0k" RESC1608X05N 9243.06,12923.47 r180 top value=1MΩ(1%)
R118 "10.0k" RESC1608X05N 9300,12970 r0 top value=1MΩ(1%)
R119 "10.0k" RESC1608X05N 9430,12760 r180 top value=1MΩ(1%)
R120 "10.0k" RESC1608X05N 9430,12713.5 r180 top value=1MΩ(1%)
R121 "10.0k" RESC1608X05N 11648.89,12929 r180 top value=1MΩ(1%)
R122 "0" RESC1608X05N 11467.92,12802.12 r90 top value=1MΩ(1%)
R123 "10.0k" RESC1608X05N 11521.97,12802.12 r90 top value=1MΩ(1%)
R124_1 "0" RESC1608X05N 2512.06,10993.24 r270 bottom value=1MΩ(1%) (schematic designator R124)
R124_2 "0" RESC1608X05N 14953.09,12827 r90 bottom value=1MΩ(1%) (schematic designator R124)
R125_1 "20" RESC1608X05N 2716.39,10903.39 r270 bottom value=1MΩ(1%) (schematic designator R125)
R125_2 "20" RESC1608X05N 14748.77,12916.85 r90 bottom value=1MΩ(1%) (schematic designator R125)
R126_1 "20" RESC1608X05N 2646.17,10903.39 r270 bottom value=1MΩ(1%) (schematic designator R126)
R126_2 "20" RESC1608X05N 14818.99,12916.85 r90 bottom value=1MΩ(1%) (schematic designator R126)
R127_1 "0" RESC1608X05N 2980,10999.92 r270 bottom value=1MΩ(1%) (schematic designator R127)
R127_2 "0" RESC1608X05N 14390,12827 r90 bottom value=1MΩ(1%) (schematic designator R127)
R128_1 "20" RESC1608X05N 3184.32,10910.07 r270 bottom value=1MΩ(1%) (schematic designator R128)
R128_2 "20" RESC1608X05N 14185.68,12916.85 r90 bottom value=1MΩ(1%) (schematic designator R128)
R129_1 "20" RESC1608X05N 3114.11,10910.07 r270 bottom value=1MΩ(1%) (schematic designator R129)
R129_2 "20" RESC1608X05N 14255.89,12916.85 r90 bottom value=1MΩ(1%) (schematic designator R129)
R130_1 "0" RESC1608X05N 2005.15,10993.24 r270 bottom value=1MΩ(1%) (schematic designator R130)
R130_2 "0" RESC1608X05N 15480,12817 r90 bottom value=1MΩ(1%) (schematic designator R130)
R131_1 "20" RESC1608X05N 2209.48,10903.39 r270 bottom value=1MΩ(1%) (schematic designator R131)
R131_2 "20" RESC1608X05N 15275.68,12906.85 r90 bottom value=1MΩ(1%) (schematic designator R131)
R132_1 "20" RESC1608X05N 2139.26,10903.39 r270 bottom value=1MΩ(1%) (schematic designator R132)
R132_2 "20" RESC1608X05N 15345.89,12906.85 r90 bottom value=1MΩ(1%) (schematic designator R132)
R133_1 "0.005" RESC1608X05N 2151.5,11441.5 r180 bottom value=1MΩ(1%) (schematic designator R133)
R133_2 "0.005" RESC1608X05N 14695.73,11750.57 r180 bottom value=1MΩ(1%) (schematic designator R133)
R134_1 "100k" RESC1608X05N 2301.11,11468.7 r270 bottom value=1MΩ(1%) (schematic designator R134)
R134_2 "100k" RESC1608X05N 14845.34,11777.77 r270 bottom value=1MΩ(1%) (schematic designator R134)
R135_1 "0" RESC1608X05N 2080.45,11467.93 r90 bottom value=1MΩ(1%) (schematic designator R135)
R135_2 "0" RESC1608X05N 14624.68,11777 r90 bottom value=1MΩ(1%) (schematic designator R135)
R136_1 "0" RESC1608X05N 2225.64,11468.24 r90 bottom value=1MΩ(1%) (schematic designator R136)
R136_2 "0" RESC1608X05N 14769.87,11777.31 r90 bottom value=1MΩ(1%) (schematic designator R136)
R137_1 "4.22k" RESC1608X05N 2270,11591.5 r0 bottom value=1MΩ(1%) (schematic designator R137)
R137_2 "4.22k" RESC1608X05N 14814.23,11900.57 r0 bottom value=1MΩ(1%) (schematic designator R137)
R138_1 "0" RESC1608X05N 2133,11891.5 r0 bottom value=1MΩ(1%) (schematic designator R138)
R138_2 "0" RESC1608X05N 14677.23,12200.57 r0 bottom value=1MΩ(1%) (schematic designator R138)
R139_1 "0.005" RESC1608X05N 2665.77,11441.5 r180 bottom value=1MΩ(1%) (schematic designator R139)
R139_2 "0.005" RESC1608X05N 14770,11190.57 r180 bottom value=1MΩ(1%) (schematic designator R139)
R140_1 "100k" RESC1608X05N 2811.11,11468.7 r270 bottom value=1MΩ(1%) (schematic designator R140)
R140_2 "100k" RESC1608X05N 14915.34,11217.77 r270 bottom value=1MΩ(1%) (schematic designator R140)
R141_1 "0" RESC1608X05N 2585.77,11470.93 r90 bottom value=1MΩ(1%) (schematic designator R141)
R141_2 "0" RESC1608X05N 14690,11220 r90 bottom value=1MΩ(1%) (schematic designator R141)
R142_1 "0" RESC1608X05N 2735.64,11468.24 r90 bottom value=1MΩ(1%) (schematic designator R142)
R142_2 "0" RESC1608X05N 14839.87,11217.31 r90 bottom value=1MΩ(1%) (schematic designator R142)
R143_1 "4.22k" RESC1608X05N 2780,11591.5 r0 bottom value=1MΩ(1%) (schematic designator R143)
R143_2 "4.22k" RESC1608X05N 14884.23,11340.57 r0 bottom value=1MΩ(1%) (schematic designator R143)
R144_1 "0" RESC1608X05N 2643,11891.5 r0 bottom value=1MΩ(1%) (schematic designator R144)
R144_2 "0" RESC1608X05N 14747.23,11640.57 r0 bottom value=1MΩ(1%) (schematic designator R144)
R145_1 "0.005" RESC1608X05N 3116.82,11441.5 r180 bottom value=1MΩ(1%) (schematic designator R145)
R145_2 "0.005" RESC1608X05N 14311.05,11190.57 r180 bottom value=1MΩ(1%) (schematic designator R145)
R146_1 "100k" RESC1608X05N 3266.43,11468.7 r270 bottom value=1MΩ(1%) (schematic designator R146)
R146_2 "100k" RESC1608X05N 14460.66,11217.77 r270 bottom value=1MΩ(1%) (schematic designator R146)
R147_1 "0" RESC1608X05N 3045.77,11467.93 r90 bottom value=1MΩ(1%) (schematic designator R147)
R147_2 "0" RESC1608X05N 14240,11217 r90 bottom value=1MΩ(1%) (schematic designator R147)
R148_1 "0" RESC1608X05N 3190.96,11468.24 r90 bottom value=1MΩ(1%) (schematic designator R148)
R148_2 "0" RESC1608X05N 14385.19,11217.31 r90 bottom value=1MΩ(1%) (schematic designator R148)
R149_1 "4.22k" RESC1608X05N 3235.32,11591.5 r0 bottom value=1MΩ(1%) (schematic designator R149)
R149_2 "4.22k" RESC1608X05N 14429.55,11340.57 r0 bottom value=1MΩ(1%) (schematic designator R149)
R150_1 "0" RESC1608X05N 3098.32,11891.5 r0 bottom value=1MΩ(1%) (schematic designator R150)
R150_2 "0" RESC1608X05N 14292.55,11640.57 r0 bottom value=1MΩ(1%) (schematic designator R150)
TP1 "I3" "PCB 1.32mm TestPoint" 7070,12710 r0 top
TP2 "I1" "PCB 1.32mm TestPoint" 7070,12550 r0 top
TP3 "I2" "PCB 1.32mm TestPoint" 6780,12710 r0 top
TP4 "VDC" "PCB 1.32mm TestPoint" 6790,12550 r0 top
TP5 "VC_2A" "PCB 1.32mm TestPoint" 9990,12200 r0 top
TP6 "VC_2B" "PCB 1.32mm TestPoint" 9000,12180 r0 top
TP7 "VC_2C" "PCB 1.32mm TestPoint" 7950,12170 r0 top
TP8 "VC_1A" "PCB 1.32mm TestPoint" 6960,12120 r0 top
TP9 "VC_1B" "PCB 1.32mm TestPoint" 5980,12130 r90 top
TP10 "VC_1C" "PCB 1.32mm TestPoint" 4910,12120 r90 top
TP12 "PWMEN1" "PCB 1.32mm TestPoint" 7700,13440 r90 top
TP13 "I1" "PCB 1.32mm TestPoint" 5470,12470 r90 top
TP14 "I2" "PCB 1.32mm TestPoint" 5470,12630 r90 top
TP15 "I3" "PCB 1.32mm TestPoint" 5170,12460 r90 top
TP16 "VDC" "PCB 1.32mm TestPoint" 5180,12630 r90 top
TP18 "PWMEN2" "PCB 1.32mm TestPoint" 9610,13240 r90 top
TP19 "GND" "1.9mm Hole" 4440,13380 r90 top
U1 "4ch Op Amp" SOIC-14 2518.11,12318.86 r0 top
U2 "4ch Op Amp" SOIC-14 1502.6,12288.86 r180 top
U3 "4ch Op Amp" SOIC-14 12010,12220 r0 top
U4 "4ch Op Amp" SOIC-14 11070,12130 r180 top
U5_1 "LV25P" LV-25-P 6920,11350 r90 top (schematic designator U5)
U5_2 "LV25P" LV-25-P 5870,11350 r90 top (schematic designator U5)
U6_1 "LV25P" LV-25-P 10070,11350 r90 top (schematic designator U6)
U6_2 "LV25P" LV-25-P 9020,11350 r90 top (schematic designator U6)
U6_3 "LV25P" LV-25-P 7970,11350 r90 top (schematic designator U6)
U7 "REF3333AIDBZR" DBZ0003A_L 12443.82,13077.76 r0 top
U8 "REF3333AIDBZR" DBZ0003A_L 12026.66,12982.24 r180 top
U9 "LM5017MRX/NOPB" DDA8_3P1X2P41 13070,13289 r180 top
U11 "LP38691SD-3.3/NOPB" FP-NGG0006A-MFG 12437.98,13361.79 r90 top
U13_1 "TLV3201AIDBVR" SOT-23-5_L3.0-W1.7-P0.95-LS2.8-BR 2681.32,11697.49 r0 top (schematic designator U13)
U13_2 "TLV3201AIDBVR" SOT-23-5_L3.0-W1.7-P0.95-LS2.8-BR 11382.81,13219.71 r0 top (schematic designator U13)
U14_1 "SN74LVC1G332DCKR" FP-DCK0006A-MFG 2777.12,11487.72 r0 top (schematic designator U14)
U14_2 "SN74LVC1G332DCKR" FP-DCK0006A-MFG 11478.61,13009.93 r0 top (schematic designator U14)
U15_1 "TLV3201AIDBVR" SOT-23-5_L3.0-W1.7-P0.95-LS2.8-BR 2531.32,11497.49 r0 top (schematic designator U15)
U15_2 "TLV3201AIDBVR" SOT-23-5_L3.0-W1.7-P0.95-LS2.8-BR 11232.81,13019.71 r0 top (schematic designator U15)
U16_1 "TLV3201AIDBVR" SOT-23-5_L3.0-W1.7-P0.95-LS2.8-BR 3051.32,11697.49 r0 top (schematic designator U16)
U16_2 "TLV3201AIDBVR" SOT-23-5_L3.0-W1.7-P0.95-LS2.8-BR 11752.81,13219.71 r0 top (schematic designator U16)
U17 "SN74AVC8T245RHLR" RHL0024A 2360,10309.49 r270 top
U18 "SN74LVC1G32DCKR" FP-DCK0005A-IPC_A 2950.01,11313.57 r0 top
U19 "SN74AVC8T245RHLR" RHL0024A 9590,12825.2 r0 top
U20 "SN74LVC1G32DCKR" FP-DCK0005A-IPC_A 11651.5,12835.79 r0 top
U21_1 "LMG5200MOFT" FP-MOF0009A-MFG 2682.06,11203.24 r180 bottom (schematic designator U21)
U21_2 "LMG5200MOFT" FP-MOF0009A-MFG 14783.09,12617 r0 bottom (schematic designator U21)
U22_1 "LMG5200MOFT" FP-MOF0009A-MFG 3150,11209.92 r180 bottom (schematic designator U22)
U22_2 "LMG5200MOFT" FP-MOF0009A-MFG 14220,12617 r0 bottom (schematic designator U22)
U23_1 "LMG5200MOFT" FP-MOF0009A-MFG 2175.15,11203.24 r180 bottom (schematic designator U23)
U23_2 "LMG5200MOFT" FP-MOF0009A-MFG 15310,12607 r0 bottom (schematic designator U23)
U24_1 "INA240A1PW" PW0008A_N_TEX 2153,11705.82 r90 bottom (schematic designator U24)
U24_2 "INA240A1PW" PW0008A_N_TEX 14697.23,12014.9 r90 bottom (schematic designator U24)
U25_1 "INA240A1PW" PW0008A_N_TEX 2663,11705.82 r90 bottom (schematic designator U25)
U25_2 "INA240A1PW" PW0008A_N_TEX 14767.23,11454.9 r90 bottom (schematic designator U25)
U26_1 "INA240A1PW" PW0008A_N_TEX 3118.32,11705.82 r90 bottom (schematic designator U26)
U26_2 "INA240A1PW" PW0008A_N_TEX 14312.55,11454.9 r90 bottom (schematic designator U26)
VB "LV25P" LV-25-P 4820,11350 r90 top (schematic designator U5)

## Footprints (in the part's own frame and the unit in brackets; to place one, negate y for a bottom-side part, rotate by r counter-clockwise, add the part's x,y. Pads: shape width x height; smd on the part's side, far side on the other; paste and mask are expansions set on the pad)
"1.9mm Hole" [mm] "Through hole terminal pin"
  round 3.5 hole 1.9: 1(0,0)
"3 Pin Terminal" [mm] "WURTH ELEKTRONIK 691102710003"
  rect 2.5x2.5 hole 1.3: 1(-5,0)
  round 2.5 hole 1.3: 2(0,0) 3(5,0)
  silkscreen extent -7.63,-3.78 7.61,4.22, body extent -7.63,-3.3 7.61,4.2, height 10
"4mH Custom" [mm] "4mH Custom"
  oval 3.2x3.6 hole 1.8: 1(-10.25,0) 2(10.25,0)
  silkscreen extent -13.21,-32.13 13.21,32.13
"380uH Custom" [mm] "380uH Custom"
  round 3 hole 1.8: 1(-8.16,0) 2(8.16,0)
  silkscreen extent -10.16,-18.67 10.29,18.67, body extent -8.25,-16.21 8.25,16.21, height 34.1
"0805 Capacitor" [mm]
  rect 1.02x1.47 smd: 1(-0.95,0) 2(0.95,0)
  silkscreen extent -1.91,-1.14 1.91,1.14, body extent -1,-0.63 1,0.63, height 0.94
"0805 Resistor" [mm]
  rect 1.02x1.47 smd: 1(-0.95,0) 2(0.95,0)
  silkscreen extent -1.91,-1.14 1.91,1.14, body extent -1,-0.63 1,0.63, height 0.65
"1206 Capacitor" [mm]
  rect 1.5x2.5 smd: 1(-1.7,0) 2(1.7,0)
  silkscreen extent -0.5,-0.85 0.5,0.85, body extent -1.6,-0.8 1.6,0.8, height 0.89
"1206 Resistor" [mm]
  rect 1.5x2.5 smd: 1(-1.7,0) 2(1.7,0)
  silkscreen extent -0.5,-0.85 0.5,0.85, body extent -1.55,-0.8 1.55,0.8, height 0.65
"2512 Resistor" [mm]
  rect 2x4 smd: 1(-3,0) 2(3,0)
  silkscreen extent -1.6,-1.7 1.6,1.7, body extent -3.2,-1.6 3.2,1.6, height 0.91
"CAP 1.5*4*8" [mm] "脚距1.5mm直径4mm高度8mm                    淘宝ID:黄晶宝石"
  rect 1.2x1.2 hole 0.6: 1(-0.75,0)
  round 1.2 hole 0.6: 2(0.75,0)
  silkscreen extent -2.2,-2.2 2.41,2.2, body extent -2,-2 2.02,2, height 8.04
CAPC1608X06N [mm] "Chip Capacitor, 2-Leads, Body 1.60x0.80mm, IPC Medium Density"
  rect 0.6x0.95 smd: 1(-0.8,0) 2(0.8,0)
  silkscreen extent -0.15,-0.38 0.15,0.38, body extent -0.8,-0.4 0.8,0.4, height 0.6
"CM Choke Custom" [mm] "CM Choke Custom"
  round 3 hole 1.8: 1(-10.55,16) 2(-10.55,0) 3(-10.55,-16) 4(10.55,16) 5(10.55,0) 6(10.55,-16)
  silkscreen extent -13.84,-23.62 13.84,23.62
DBZ0003A_L [mm] "SOT23, 3-Leads, Body 3.04x1.4mm, Pitch 0.95mm, IPC High Density"
  rrect18% 0.8x0.55 smd: 1(-1.1,0.95) 2(-1.1,-0.95) 3(1.1,0)
  silkscreen extent -1.22,-1.5 0.7,1.9, body extent -1.26,-1.46 1.26,1.46, height 0.96
DDA8_3P1X2P41 [mil]
  rect 78x21 smd paste-39 mask-39: 1(-97,75) 2(-97,25) 3(-97,-25) 4(-97,-75) 5(97,-75) 6(97,-25) 7(97,25) 8(97,75)
  rect 95x122 smd paste-60.5 mask-60.5: 9(0,0)
  round 20 / inner round 60 / far side round 20 hole 10 paste-99999 mask-10: V(-31,31) V(-31,0) V(-31,-31) V(0,31) V(0,0) V(0,-31) V(31,31) V(31,0) V(31,-31)
  silkscreen extent -56,-98 56,98, body extent -122,-99 122,99, height 67
DG1282-5.0 [mil]
  rect 120x200 hole 50: 1(-100,0)
  oval 120x200 hole 50: 2(100,0)
  silkscreen extent -205,-205 205,191
"Film Capacitor PHE450HF7220JR06L2" [mm] "KEMET PHE450 Metallised Polypropylene Film Capacitor, 180 V ac, 250 V dc, ?%, 2.2礔, Through Hole"
  round 2.5 hole 1.27: 1(0,13.75) 2(0,-13.75)
  silkscreen extent -7.25,-15.75 7.25,15.75, body extent -7.24,-15.62 7.26,15.88, height 24.01
FP-DCK0005A-IPC_A [mm]
  rect 1.677x0.416 smd paste+0 mask+0: 1(-0.914,0.65)
  rrect100% 1.677x0.416 smd paste+0 mask+0: 2(-0.914,0) 3(-0.914,-0.65) 4(0.914,-0.65) 5(0.914,0.65)
  silkscreen extent -2.45,-1.25 1.05,1.25
FP-DCK0006A-MFG [mm]
  rect 0.9x0.4 smd paste-1000 mask+0: 1(-1.1,0.65) 2(-1.1,0) 3(-1.1,-0.65) 4(1.1,-0.65) 5(1.1,0) 6(1.1,0.65)
  silkscreen extent -2.22,-1.07 0.27,1.07, body extent -1.65,-1.33 1.65,1.33, height 0.25
FP-MOF0009A-MFG [mm]
  rrect14% 0.7x4.25 smd paste-1000 mask+0: 1(-2.55,1.78) 8(2.55,1.78)
  rrect20% 0.7x0.5 smd paste+0 mask+0: 2(-2.55,-2.05) 3(-2.55,-3.25) 6(2.55,-3.25) 7(2.55,-2.05)
  rrect20% 0.5x0.7 smd paste+0 mask+0: 4(-0.9,-3.55) 5(0.9,-3.55)
  rrect10% 1.05x4.25 smd paste-1000 mask+0: 9(0,1.78)
  silkscreen extent -3.78,-4.05 3.05,4.05, body extent -3,-4 3,4, height 2
FP-NGG0006A-MFG [mm]
  rect 0.6x0.35 smd paste+0 mask+0: 1(-1.4,0.95) 2(-1.4,0) 3(-1.4,-0.95) 4(1.4,-0.95) 5(1.4,0) 6(1.4,0.95)
  rect 1.6x2.1 smd paste+0 mask+0: 7(0,0)
  silkscreen extent -2.4,-1.55 1.55,1.55, body extent -1.8,-1.65 1.8,1.65, height 0.25
HDR1X2 [mm] "Connector; Header; 2 Position"
  rect 1.5x1.5 hole 0.9: 1(0,0)
  round 1.5 hole 0.9: 2(2.54,0)
  silkscreen extent -1.27,-1.27 3.81,1.27
LV-25-P [mm]
  round 2.2 hole 1.2: 1(-10.16,-7.62) 2(10.16,-7.62) 3(10.16,0) 5(-10.16,7.62)
  round 2.2 hole 1.2 paste-2539.97: 4(10.16,7.62)
  silkscreen extent -16.54,-13 14.6,13, body extent -13.6,-13 15.6,13, height 16.4
"M5 Earthing Hole" [mm] "M5 Mounting Hole"
  round 10 hole 5.5: 1(0,0)
  silkscreen extent -6.22,-6.22 6.22,6.22
"M5 Mounting Hole" [mm] "M5 Mounting Hole"
  round 5.5 hole 5.5: 1(0,0)
  silkscreen extent -5.5,-5.5 5.5,5.5
NR2520 [mm] "2.5mm*2.0mm*1.0mm(长*宽*高）"
  rect 0.85x2 smd: 1(-0.825,0) 2(0.825,0)
  silkscreen extent -1.52,-1.27 1.52,1.27, body extent -1.25,-1 1.25,1, height 1.1
NR4018 [mm] "4.0mm*4.0mm*1.8mm(长*宽*高）"
  rect 1.1x3.7 smd: 1(-1.5,0) 2(1.5,0)
  silkscreen extent -2.29,-2.03 2.29,2.03, body extent -2,-2 2,2, height 1.9
"PCB 1.32mm TestPoint" [mm] "20-313143 PCB Test Point, White, Through Hole Mount, 1.32 mm, Phosphor Bronze, Tin Plated Contacts"
  round 2.5 hole 1.32: 1(0,0)
  body extent -1.15,-1.15 1.15,1.15, height 5
PW0008A_N_TEX [mil]
  rect 59x18 smd paste+0 mask+2: 1(-114.17,38.39) 2(-114.17,12.8) 3(-114.17,-12.8) 4(-114.17,-38.39) 5(114.17,-38.39) 6(114.17,-12.8) 7(114.17,12.8) 8(114.17,38.39)
  silkscreen extent -169,-64 92,64, body extent -130,-59 130,59, height 47
RAD-0.3 [mm] "Radial Cap, Thru-Hole; 2 Leads; 0.3 in Pin Spacing"
  round 1.4 hole 0.7: 1(-3.81,0) 2(3.81,0)
  silkscreen extent -5.71,-1.91 5.71,1.91
RESC1608X05N [mm] "Chip Resistor, 2-Leads, Body 1.60x0.80mm, IPC Medium Density"
  rect 0.6x0.85 smd: 1(-0.838,0) 2(0.838,0)
  silkscreen extent -0.2,-0.33 0.2,0.33, body extent -0.8,-0.4 0.8,0.4, height 0.5
RHL0024A [mm]
  oval 0.24x0.6 smd paste-0.102 mask+0.051: 1(-0.75,2.65) 12(-0.75,-2.65) 13(0.75,-2.65) 24(0.75,2.65)
  oval 0.6x0.24 smd paste-0.102 mask+0.051: 2(-1.65,2.25) 3(-1.65,1.75) 4(-1.65,1.25) 5(-1.65,0.75) 6(-1.65,0.25) 7(-1.65,-0.25) 8(-1.65,-0.75) 9(-1.65,-1.25) 10(-1.65,-1.75) 11(-1.65,-2.25) 14(1.65,-2.225) 15(1.65,-1.725) 16(1.65,-1.225) 17(1.65,-0.725) 18(1.65,-0.225) 19(1.65,0.275) 20(1.65,0.775) 21(1.65,1.275) 22(1.65,1.775) 23(1.65,2.275)
  rect 2.05x4.05 smd paste-2.012 mask+0.051: 25(0,0)
  round 0.5 / inner round 1.524 / far side round 0.5 hole 0.203 paste-2539.97 mask+0.076: V(-0.775,0) V(0.775,0)
  round 0.5 / inner round 1.524 / far side round 0.5 hole 0.203 paste-2539.97 mask+0.051: V(0,1.9) V(0,-1.9)
  Top Layer region: -0.395,-2.024 -0.395,-2.225 0.395,-2.225 0.395,-2.024
  Top Layer region: -0.396,2.75 -0.396,2 -0.154,2 -0.154,2.75
  Top Layer region: 0.152,2.75 0.152,2 0.394,2 0.394,2.75
  Top Layer region: -0.395,2.225 -0.395,2.024 0.395,2.024 0.395,2.225
  Top Layer region: -0.152,-2.75 -0.152,-2 -0.394,-2 -0.394,-2.75
  Top Layer region: 0.396,-2.75 0.396,-2 0.154,-2 0.154,-2.75
  silkscreen extent -1.95,-2.95 1.95,2.95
